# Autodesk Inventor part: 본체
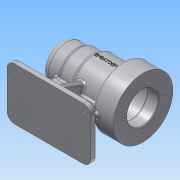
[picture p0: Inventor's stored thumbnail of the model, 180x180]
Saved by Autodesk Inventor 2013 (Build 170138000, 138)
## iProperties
Created: 2016-06
Part Number: 본체
Material: 알루미늄 6061
Document SubType Name: Modeling
Designer: Administrator
Density: 2.71 g/cm^3
Mass: 777.873 g
Surface Area: 688.973 cm^2
Volume: 287.038 cm^3
Author: Administrator
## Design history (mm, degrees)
sketch "스케치1"
  geometry: L1 (-56, 0)-(56, 0); L2 (-56, 0)-(-56, 25); L3 (-56, 25)-(-31, 25); L4 (-31, 25)-(-31, 27); L5 (-11, 27)-(-11, 30); L6 (28, 40)-(56, 40); L7 (56, 40)-(56, 0); L8 (-31, 27)-(-11, 27); L9 (-11, 30)-(-11, 30); L10 (-11, 30)-(28, 30); L11 (28, 30)-(28, 40); L12 (28, 40)-(28, 40); 2 further points
  constraints: 24 end point, 6 parallel, 5 perpendicular, 1 coincident, 1 horizontal, 1 midpoint
  dimensions: "d0" = 112 distance of L1.start L1.end; "d2" = 25 distance between parallel lines of L4 L2; "d3" = 50 diameter of L3 L1; "d9" = 80 diameter of L6 L1; "d11" = 45 distance between parallel lines of L9 L2; "d12" = 84 distance between parallel lines of L11 L2; "d13" = 60 diameter of L10 L1; "d14" = 54 diameter of L8 L1
revolve "회전1" sketch "스케치1" stored, may be unused: angle "d15" = 90 deg
sketch "스케치2"
  geometry: L1 (-56, -25)-(-56, 25) reference; L2 (-56, 25)-(-31, 25) reference; L3 (-31, 25)-(-31, 27) reference; L4 (-31, 27)-(-11, 27) reference; L5 (-11, 27)-(-11, 30) reference; L6 (-11, 30)-(28, 30) reference; L7 (28, 30)-(28, 40) reference; L8 (28, 40)-(56, 40) reference; L9 (56, 40)-(56, -40) reference; L10 (56, -40)-(28, -40) reference; L11 (28, -40)-(28, -30) reference; L12 (28, -30)-(-11, -30) reference; L13 (-11, -30)-(-11, -27) reference; L14 (-11, -27)-(-31, -27) reference; L15 (-31, -27)-(-31, -25) reference; L16 (-31, -25)-(-56, -25) reference; L17 (56, 0)-(-47, 0); L18 (56, 0)-(56, 21); L19 (56, 21)-(41, 21); L20 (41, 21)-(41, 24); L21 (41, 24)-(-13, 24); L22 (-13, 21)-(-25, 21); L23 (-13, 24)-(-13, 21); L24 (-25, 21)-(-25, 17.5); L25 (-47, 16)-(-47, 0); L26 (-25, 17.5)-(-43, 17.5); L27 (-43, 17.5)-(-43, 16); L28 (-43, 16)-(-47, 16); 1 further point
  constraints: 24 end point, 6 perpendicular, 3 parallel, 1 horizontal, 1 midpoint, 1 point on line
  dimensions: "d17" = 103 distance of L17.start L17.end; "d18" = 15 distance between parallel lines of L20 L18; "d19" = 42 diameter of L19 L17; "d20" = 54 distance between parallel lines of L23 L20; "d21" = 48 diameter of L21 L17; "d22" = 12 distance between parallel lines of L23 L24; "d23" = 42 diameter of L22 L17; "d24" = 18 distance between parallel lines of L24 L27; "d25" = 35 diameter of L26 L17; "d26" = 32 diameter of L28 L17
revolve "회전2" sketch "스케치2" stored, may be unused: angle "d27" = 90 deg
sketch "스케치3"
  geometry: L1 (-56, -25)-(-56, 25) reference; L2 (-56, 25)-(-31, 25) reference; L3 (-31, 25)-(-31, 27) reference; L4 (-31, 27)-(-11, 27) reference; L5 (-11, 27)-(-11, 30) reference; L6 (-11, 30)-(28, 30) reference; L7 (28, 30)-(28, 40) reference; L8 (28, 40)-(56, 40) reference; L9 (56, 40)-(56, 21) reference; L10 (56, 21)-(41, 21) reference; L11 (41, 21)-(41, 24) reference; L12 (41, 24)-(-13, 24) reference; L13 (-13, 24)-(-13, 21) reference; L14 (-13, 21)-(-25, 21) reference; L15 (-25, 21)-(-25, 17.5) reference; L16 (-25, 17.5)-(-43, 17.5) reference; L17 (-43, 17.5)-(-43, 16) reference; L18 (-43, 16)-(-47, 16) reference; L19 (-47, 16)-(-47, -16) reference; L20 (-47, -16)-(-43, -16) reference; L21 (-43, -16)-(-43, -17.5) reference; L22 (-43, -17.5)-(-25, -17.5) reference; L23 (-25, -17.5)-(-25, -21) reference; L24 (-25, -21)-(-13, -21) reference; L25 (-13, -21)-(-13, -24) reference; L26 (-13, -24)-(41, -24) reference; L27 (41, -24)-(41, -21) reference; L28 (41, -21)-(56, -21) reference; L29 (56, -21)-(56, -40) reference; L30 (56, -40)-(28, -40) reference; L31 (28, -40)-(28, -30) reference; L32 (28, -30)-(-11, -30) reference; L33 (-11, -30)-(-11, -27) reference; L34 (-11, -27)-(-31, -27) reference; L35 (-31, -27)-(-31, -25) reference; L36 (-31, -25)-(-56, -25) reference; L37 (-47, 0)-(-53, 0); L38 (-53, 0)-(-53, 10.5); L39 (-53, 10.5)-(-47, 10.5); 1 further point
  constraints: 6 end point, 2 perpendicular, 1 midpoint, 1 parallel, 1 point on line
  dimensions: "d28" = 3 distance between parallel lines of L38 L1; "d29" = 21 diameter of L39 L37
revolve "회전3" sketch "스케치3" stored, may be unused: angle "d30" = 90 deg
chamfer "모따기1" distance "d33" = 1; stored, may be unused: second distance "d34" = 2, angle "d35" = 45 deg
sketch "스케치4"
  geometry: L1 (0, 0)-(0, 26); C1 r 22 at (0, 0) reference; 1 further point
  constraints: 2 end point, 1 coincident, 1 vertical
  dimensions: "d36" = 26 distance of L1.start L1.end
hole "구멍1" sketch "스케치4" at (0, 26) diameter "d37" = 3.242; stored, may be unused: countersink angle "d41" = 90 deg, drill point angle "d43" = 118 deg; dims "d38" = 8, "d39" = 4, "d40" = 2, "d42" = 11
node "작업 평면1"
sketch "스케치5"
  geometry: L1 (56, -35)-(-56, -35); L2 (-56, -35)-(-56, 35); L3 (-56, 35)-(56, 35); L4 (56, 35)-(56, -35); L5 (56, -35)-(-56, 35); L6 (-56, -35)-(56, 35); 3 further points
  constraints: 12 end point, 3 midpoint, 2 parallel, 1 coincident, 1 horizontal, 1 perpendicular
  dimensions: "d48" = 112 distance of L2.end L3.end; "d49" = 70 distance of L1.end L2.end
extrude "돌출1" join sketch "스케치5" distance "d50" = 10; taper "d51" = 0 deg
sketch "스케치6"
  geometry: L1 (-56, 35)-(-56, -35) reference; L2 (36, -4)-(-36, -4); L3 (-36, -4)-(-36, 4); L4 (-36, 4)-(36, 4); L5 (36, 4)-(36, -4); L6 (36, -4)-(-36, 4); L7 (-36, -4)-(36, 4); L8 (4, -28)-(-4, -28); L9 (-4, -28)-(-4, 28); L10 (-4, 28)-(4, 28); L11 (4, 28)-(4, -28); L12 (4, -28)-(-4, 28); L13 (-4, -28)-(4, 28); L14 (56, 35)-(56, -35) reference; L15 (56, -35)-(-56, -35) reference; L16 (-56, -35)-(-56, 35) reference; L17 (-56, 35)-(56, 35) reference; 1 further point
  constraints: 24 end point, 4 midpoint, 4 parallel, 2 horizontal, 2 perpendicular
  dimensions: "d52" = 8 distance of L2.end L3.end; "d53" = 8 distance of L9.end L10.end; "d54" = 20 distance between parallel lines of L3 L1; "d55" = 7 distance between parallel lines of L10 L17
extrude "돌출2" join sketch "스케치6" stored distance "d56" = 10; taper "d57" = 0 deg
feature "면 기울기1" dims angle "d58" = 20 deg
fillet "모깎기3" dims "d59" = 10
fillet "모깎기4" dims "d60" = 3
fillet "모깎기5" dims "d61" = 3
fillet "모깎기8" dims "d64" = 3
fillet "모깎기10" dims "d66" = 3
sketch "스케치7"
  geometry: A1 r 7 centre (-46, 25) between (-46, 32) and (-53, 25) reference; A2 r 7 centre (-46, -25) between (-53, -25) and (-46, -32) reference; A3 r 7 centre (46, -25) between (46, -32) and (53, -25) reference; A4 r 7 centre (46, 25) between (53, 25) and (46, 32) reference; 5 further points
  constraints: 4 coincident
hole "구멍2" sketch "스케치7" at (-46, 25), (-46, -25), (46, 25), (46, -25) diameter "d67" = 3; stored, may be unused: countersink angle "d71" = 90 deg, drill point angle "d73" = 118 deg; dims "d68" = 5, "d69" = 9, "d70" = 4, "d72" = 11
node "작업 평면2"
fillet "모깎기11" dims "d78" = 3
node "작업 평면3"
sketch "스케치9"
  geometry: L1 (56, 1.621)-(56, -1.621) reference; 2 further points
  constraints: 1 horizontal alignment, 1 other
  dimensions: "d80" = 48 distance from line of point (8, 0) L1
feature "엠보싱2" sketch "스케치9" dims "d81" = 0.5, "d82" = 0
fillet "모깎기12" dims "d83" = 3
fillet "모깎기14" dims "d85" = 3
fillet "모깎기16" dims "d87" = 3
fillet "모깎기17" dims "d88" = 0.3
fillet "모깎기18" dims "d89" = 3
chamfer "모따기2" distance "d90" = 4; stored, may be unused: second distance "d91" = 2, angle "d92" = 45 deg
node "솔리드1"
pattern_circular "원형 패턴1" dims angle "d45" = 360 deg
node "절단 모서리 투영1"
node "절단 모서리 투영2"
node "절단 모서리 투영3"
